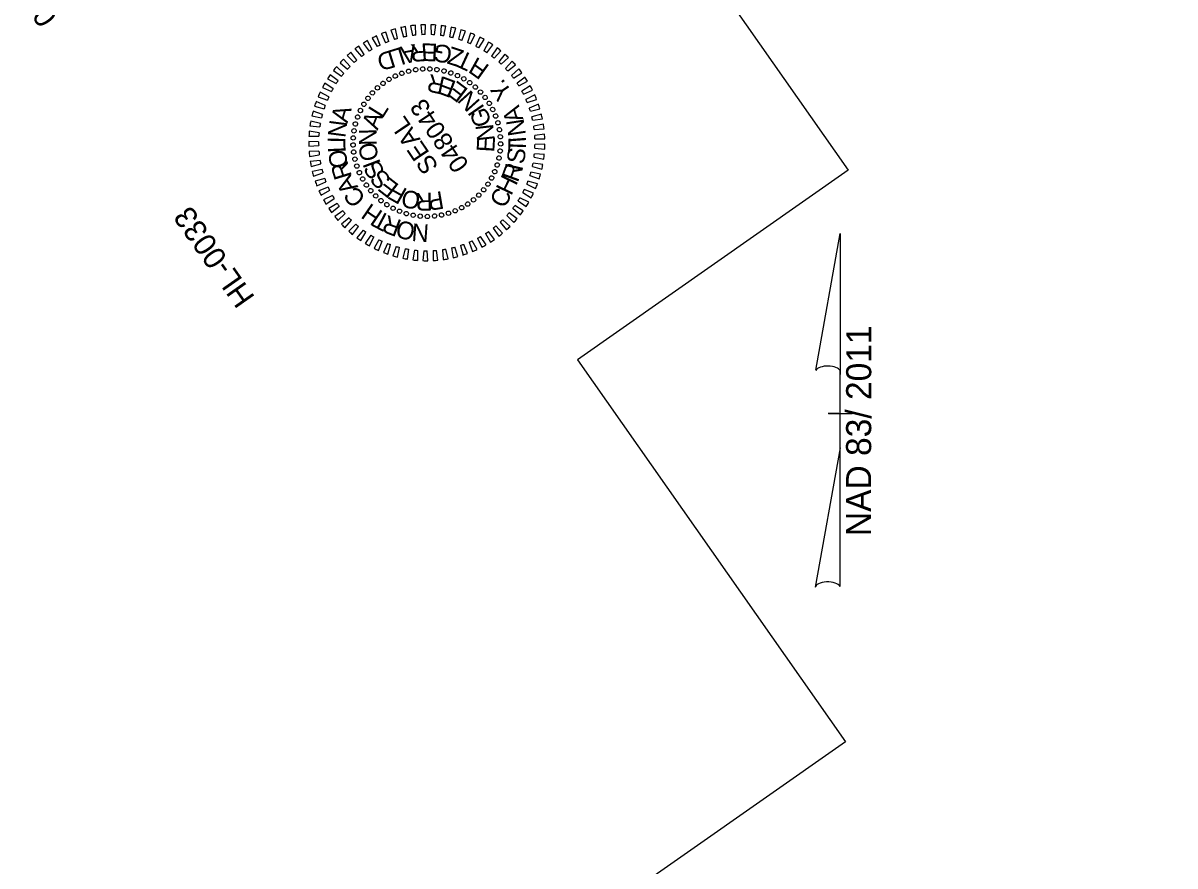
# Model space of a CAD drawing. Extents: x 2046262 to 2047823, y 758628 to 760417.
# Drawn here: x 2046261.8 to 2046652, y 759522.5 to 759808.2 of the extents above; entities that cross this region are included whole.
import ezdxf

# ---------------------------------------------------------------- set-up
doc = ezdxf.new("R2010")
doc.units = 0
for name, color, linetype in [('Prop North Arrow NAD83 for Plan Sheets CELL', 7, 'Continuous'), ('Sheet Clip Boundary CELL', 7, 'Continuous'), ('Sheet Data Field CELL', 7, 'Continuous'), ('Sheet PE Seal Cell', 7, 'Continuous')]:
    doc.layers.add(name, color=color, linetype=linetype)

msp = doc.modelspace()

# ---------------------------------------------------------------- linework, layer by layer
at = {"layer": 'Prop North Arrow NAD83 for Plan Sheets CELL'}
for p, q in [((2046530.36, 759690.47), (2046538.6, 759736.81)), ((2046538.65, 759736.81), (2046538.6, 759736.81)), ((2046538.65, 759736.81), (2046538.6, 759736.81)), ((2046538.65, 759736.81), (2046538.6, 759689.01)), ((2046538.58, 759664.21), (2046538.61, 759690.41)), ((2046538.6, 759689.01), (2046538.61, 759690.36)), ((2046534.59, 759675.81), (2046534.54, 759675.81)), ((2046538.14, 759675.81), (2046534.59, 759675.81)), ((2046534.64, 759675.81), (2046542.64, 759675.8)), ((2046538.58, 759664.21), (2046530.18, 759616.97)), ((2046538.58, 759617.16), (2046538.58, 759664.21))]:
    msp.add_line(p, q, dxfattribs=at)
for centre, start_param, end_param in [((2046534.49, 759689.97), 0.216388, 2.908219), ((2046534.41, 759616.8), 0.201328, 3.141593)]:
    msp.add_ellipse(centre, major_axis=(4.23, -0.03), ratio=0.461098, start_param=start_param, end_param=end_param, dxfattribs=at)
at = {"layer": 'Sheet Clip Boundary CELL'}
msp.add_lwpolyline([(2046953.28, 758800.94), (2047822.73, 759389.82), (2047107.57, 760411.26), (2046421.17, 759929.65), (2046541.36, 759758.35), (2046449.64, 759693.99), (2046540.41, 759564.59), (2046459.01, 759507.49)], close=True, dxfattribs=at)
at = {"layer": 'Sheet PE Seal Cell'}
for p, q in [((2046383.16, 759804.53), (2046384.61, 759801.51)), ((2046385.69, 759801.93), (2046384.69, 759805.13)), ((2046386.39, 759805.72), (2046387.58, 759802.58)), ((2046388.68, 759802.91), (2046387.97, 759806.19)), ((2046389.71, 759806.63), (2046390.63, 759803.4)), ((2046391.75, 759803.63), (2046391.32, 759806.96)), ((2046393.09, 759807.24), (2046393.73, 759803.95)), ((2046394.87, 759804.08), (2046394.73, 759807.44)), ((2046396.52, 759807.57), (2046396.87, 759804.23)), ((2046398.02, 759804.27), (2046398.17, 759807.62)), ((2046399.96, 759807.6), (2046400.03, 759804.24)), ((2046401.17, 759804.18), (2046401.61, 759807.51)), ((2046403.39, 759807.33), (2046403.17, 759803.98)), ((2046404.31, 759803.82), (2046405.03, 759807.1)), ((2046406.79, 759806.77), (2046406.28, 759803.45)), ((2046407.4, 759803.19), (2046408.4, 759806.4)), ((2046410.12, 759805.92), (2046409.33, 759802.66)), ((2046410.42, 759802.3), (2046411.69, 759805.41)), ((2046413.37, 759804.78), (2046412.3, 759801.6)), ((2046413.36, 759801.16), (2046414.89, 759804.14)), ((2046377.35, 759797.5), (2046375.57, 759800.35)), ((2046377.06, 759801.34), (2046379.02, 759798.62)), ((2046380, 759799.21), (2046378.47, 759802.2)), ((2046380.04, 759803.07), (2046381.75, 759800.18)), ((2046382.78, 759800.69), (2046381.52, 759803.8)), ((2046416.51, 759803.37), (2046415.17, 759800.3)), ((2046416.19, 759799.76), (2046417.97, 759802.6)), ((2046419.52, 759801.7), (2046417.92, 759798.75)), ((2046418.89, 759798.13), (2046420.91, 759800.81)), ((2046371.6, 759797.16), (2046374, 759794.81)), ((2046374.86, 759795.57), (2046372.84, 759798.25)), ((2046374.24, 759799.37), (2046376.42, 759796.82)), ((2046422.37, 759799.77), (2046420.52, 759796.97)), ((2046421.43, 759796.27), (2046423.68, 759798.76)), ((2046425.05, 759797.61), (2046422.97, 759794.98)), ((2046423.81, 759794.2), (2046426.26, 759796.49)), ((2046370.43, 759791.09), (2046367.98, 759793.39)), ((2046369.16, 759794.73), (2046371.75, 759792.59)), ((2046372.55, 759793.42), (2046370.31, 759795.92)), ((2046427.53, 759795.22), (2046425.23, 759792.78)), ((2046426, 759791.93), (2046428.64, 759794)), ((2046429.79, 759792.63), (2046427.29, 759790.39)), ((2046364.95, 759789.29), (2046367.87, 759787.63)), ((2046368.51, 759788.58), (2046365.88, 759790.66)), ((2046366.94, 759792.1), (2046369.7, 759790.2)), ((2046427.99, 759789.48), (2046430.8, 759791.32)), ((2046431.83, 759789.85), (2046429.14, 759787.84)), ((2046429.76, 759786.87), (2046432.72, 759788.46)), ((2046365.37, 759783.12), (2046362.41, 759784.72)), ((2046363.22, 759786.32), (2046366.26, 759784.92)), ((2046366.82, 759785.92), (2046364.02, 759787.77)), ((2046433.61, 759786.91), (2046430.77, 759785.14)), ((2046431.3, 759784.12), (2046434.38, 759785.45)), ((2046364.16, 759780.21), (2046361.08, 759781.55)), ((2046361.74, 759783.21), (2046364.9, 759782.07)), ((2046435.14, 759783.83), (2046432.15, 759782.31)), ((2046432.6, 759781.25), (2046435.78, 759782.31)), ((2046436.4, 759780.63), (2046433.29, 759779.36)), ((2046359.61, 759776.67), (2046362.92, 759776.09)), ((2046363.2, 759777.21), (2046360.02, 759778.27)), ((2046360.54, 759779.99), (2046363.78, 759779.13)), ((2046433.64, 759778.27), (2046436.91, 759779.05)), ((2046437.38, 759777.33), (2046434.17, 759776.34)), ((2046358.98, 759773.29), (2046362.32, 759773)), ((2046362.51, 759774.13), (2046359.25, 759774.92)), ((2046434.43, 759775.22), (2046437.75, 759775.72)), ((2046438.07, 759773.95), (2046434.79, 759773.24)), ((2046358.64, 759769.87), (2046361.99, 759769.86)), ((2046362.08, 759771.01), (2046358.76, 759771.51)), ((2046434.95, 759772.11), (2046438.3, 759772.32)), ((2046438.47, 759770.53), (2046435.14, 759770.11)), ((2046435.2, 759768.96), (2046438.55, 759768.89)), ((2046361.93, 759767.86), (2046358.58, 759768.07)), ((2046358.59, 759766.42), (2046361.94, 759766.71)), ((2046398.57, 759767.62), (2046398.57, 759767.62)), ((2046435.18, 759765.81), (2046438.52, 759765.45)), ((2046438.57, 759767.09), (2046435.22, 759766.96)), ((2046362.04, 759764.7), (2046358.69, 759764.63)), ((2046358.84, 759762.99), (2046362.15, 759763.56)), ((2046362.43, 759761.57), (2046359.09, 759761.22)), ((2046434.89, 759762.67), (2046438.18, 759762.02)), ((2046438.38, 759763.66), (2046435.03, 759763.81)), ((2046359.39, 759759.59), (2046362.63, 759760.44)), ((2046363.08, 759758.49), (2046359.79, 759757.85)), ((2046360.22, 759756.25), (2046363.38, 759757.38)), ((2046437.11, 759756.9), (2046433.83, 759757.62)), ((2046434.33, 759759.56), (2046437.55, 759758.64)), ((2046437.89, 759760.25), (2046434.56, 759760.69)), ((2046364, 759755.47), (2046360.77, 759754.55)), ((2046361.34, 759753), (2046364.39, 759754.39)), ((2046432.42, 759753.56), (2046435.44, 759752.09)), ((2046436.05, 759753.63), (2046432.84, 759754.63)), ((2046433.5, 759756.52), (2046436.64, 759755.32)), ((2046365.17, 759752.54), (2046362.03, 759751.35)), ((2046362.74, 759749.85), (2046365.66, 759751.5)), ((2046366.59, 759749.73), (2046363.57, 759748.27)), ((2046431.09, 759750.7), (2046433.97, 759748.98)), ((2046434.7, 759750.46), (2046431.6, 759751.73)), ((2046364.4, 759746.84), (2046367.17, 759748.73)), ((2046368.24, 759747.05), (2046365.36, 759745.33)), ((2046366.31, 759743.98), (2046368.91, 759746.1)), ((2046427.71, 759745.38), (2046430.25, 759743.19)), ((2046431.23, 759744.52), (2046428.39, 759746.31)), ((2046429.51, 759747.97), (2046432.23, 759746.01)), ((2046433.1, 759747.41), (2046430.11, 759748.95)), ((2046370.13, 759744.51), (2046367.4, 759742.56)), ((2046368.46, 759741.29), (2046370.86, 759743.63)), ((2046372.22, 759742.15), (2046369.67, 759739.97)), ((2046426.79, 759739.27), (2046424.3, 759741.52)), ((2046425.69, 759742.96), (2046428.03, 759740.56)), ((2046429.12, 759741.8), (2046426.45, 759743.82)), ((2046370.84, 759738.8), (2046373.03, 759741.34)), ((2046374.5, 759739.98), (2046372.16, 759737.59)), ((2046373.42, 759736.52), (2046375.38, 759739.24)), ((2046376.97, 759738.02), (2046374.84, 759735.43)), ((2046421.52, 759734.85), (2046419.45, 759737.5)), ((2046421.06, 759738.68), (2046422.96, 759735.92)), ((2046424.25, 759736.95), (2046421.96, 759739.4)), ((2046423.47, 759740.72), (2046425.6, 759738.13)), ((2046376.18, 759734.47), (2046377.91, 759737.35)), ((2046379.59, 759736.27), (2046377.69, 759733.5)), ((2046379.12, 759732.67), (2046380.59, 759735.69)), ((2046382.36, 759734.75), (2046380.7, 759731.84)), ((2046382.19, 759731.13), (2046383.4, 759734.26)), ((2046412.93, 759733.9), (2046414.06, 759730.74)), ((2046415.57, 759731.41), (2046413.98, 759734.36)), ((2046415.77, 759735.26), (2046417.17, 759732.21)), ((2046418.62, 759733), (2046416.78, 759735.81)), ((2046418.49, 759736.86), (2046420.15, 759733.94)), ((2046385.25, 759733.48), (2046383.84, 759730.43)), ((2046385.39, 759729.86), (2046386.32, 759733.08)), ((2046388.23, 759732.46), (2046387.09, 759729.3)), ((2046388.68, 759728.86), (2046389.34, 759732.15)), ((2046391.29, 759731.7), (2046390.43, 759728.46)), ((2046392.05, 759728.16), (2046392.42, 759731.49)), ((2046394.41, 759731.21), (2046393.83, 759727.9)), ((2046395.47, 759727.74), (2046395.55, 759731.1)), ((2046397.55, 759730.98), (2046397.26, 759727.64)), ((2046398.91, 759727.62), (2046398.7, 759730.97)), ((2046400.7, 759731.03), (2046400.7, 759727.68)), ((2046402.35, 759727.8), (2046401.85, 759731.12)), ((2046403.84, 759731.35), (2046404.13, 759728.01)), ((2046405.76, 759728.27), (2046404.98, 759731.53)), ((2046406.94, 759731.94), (2046407.51, 759728.63)), ((2046409.11, 759729.03), (2046408.05, 759732.22)), ((2046409.98, 759732.79), (2046410.83, 759729.54)), ((2046412.39, 759730.08), (2046411.06, 759733.16))]:
    msp.add_line(p, q, dxfattribs=at)
for radius, start, end in [(40, 110.308, 112.6716), (40, 105.3765, 107.7401), (40, 100.445, 102.8086), (40, 95.5135, 97.8771), (36.65, 95.7963, 97.5942), (40, 90.5819, 92.9456), (36.65, 90.8648, 92.6627), (40, 85.6504, 88.0141), (36.65, 85.9333, 87.7312), (36.65, 81.0018, 82.7997), (40, 80.7189, 83.0825), (40, 75.7874, 78.151), (40, 70.8559, 73.2195), (40, 65.9244, 68.288), (40, 125.1025, 127.4661), (40, 120.171, 122.5346), (40, 115.2395, 117.6031), (36.65, 115.5223, 117.3202), (36.65, 110.5908, 112.3887), (36.65, 105.6593, 107.4572), (36.65, 100.7278, 102.5257), (36.65, 76.0703, 77.8682), (36.65, 71.1388, 72.9367), (36.65, 66.2073, 68.0052), (36.65, 61.2758, 63.0737), (40, 60.9929, 63.3565), (40, 56.0614, 58.425), (40, 130.034, 132.3976), (36.65, 125.3854, 127.1832), (36.65, 120.4538, 122.2517), (36.65, 56.3443, 58.1422), (36.65, 51.4128, 53.2106), (40, 51.1299, 53.4935), (40, 46.1984, 48.562), (40, 139.897, 142.2606), (40, 134.9655, 137.3291), (36.65, 135.2484, 137.0463), (36.65, 130.3169, 132.1148), (36.65, 46.4812, 48.2791), (36.65, 41.5497, 43.3476), (40, 41.2669, 43.6305), (40, 36.3354, 38.699), (40, 144.8285, 147.1921), (36.65, 145.1114, 146.9093), (36.65, 140.1799, 141.9778), (36.65, 36.6182, 38.4161), (40, 31.4039, 33.7675), (40, 154.6915, 157.0552), (40, 149.76, 152.1236), (36.65, 150.0429, 151.8408), (36.65, 31.6867, 33.4846), (36.65, 26.7552, 28.5531), (40, 26.4724, 28.836), (40, 159.623, 161.9867), (36.65, 154.9744, 156.7723), (36.65, 21.8237, 23.6216), (40, 21.5408, 23.9045), (40, 16.6093, 18.973), (40, 164.5545, 166.9182), (36.65, 164.8374, 166.6353), (36.65, 159.9059, 161.7038), (36.65, 16.8922, 18.6901), (40, 11.6778, 14.0415), (40, 169.4861, 171.8497), (36.65, 169.7689, 171.5668), (36.65, 11.9607, 13.7586), (36.65, 7.0292, 8.8271), (40, 6.7463, 9.1099), (40, 174.4176, 176.7812), (36.65, 174.7004, 176.4983), (36.65, 2.0977, 3.8956), (40, 1.8148, 4.1784), (40, 179.3491, 181.7127), (36.65, 179.6319, 181.4298), (36.65, 357.1662, 358.9641), (40, 356.8833, 359.2469), (40, 184.2806, 186.6442), (40, 189.2121, 191.5757), (36.65, 184.5634, 186.3613), (36.65, 189.4949, 191.2928), (36.65, 352.2347, 354.0326), (40, 351.9518, 354.3154), (40, 194.1436, 196.5072), (36.65, 194.4264, 196.2243), (36.65, 342.3717, 344.1695), (36.65, 347.3032, 349.1011), (40, 347.0203, 349.3839), (40, 199.0751, 201.4387), (36.65, 199.358, 201.1559), (36.65, 337.4401, 339.238), (40, 337.1573, 339.5209), (40, 342.0888, 344.4524), (40, 204.0066, 206.3702), (36.65, 204.2895, 206.0874), (36.65, 209.221, 211.0189), (36.65, 332.5086, 334.3065), (40, 332.2258, 334.5894), (40, 208.9381, 211.3017), (40, 213.8696, 216.2332), (36.65, 214.1525, 215.9504), (36.65, 322.6456, 324.4435), (36.65, 327.5771, 329.375), (40, 327.2943, 329.6579), (40, 218.8011, 221.1647), (36.65, 219.084, 220.8819), (36.65, 224.0155, 225.8134), (36.65, 312.7826, 314.5805), (36.65, 317.7141, 319.512), (40, 317.4313, 319.7949), (40, 322.3628, 324.7264), (40, 223.7326, 226.0962), (40, 228.6641, 231.0278), (36.65, 228.947, 230.7449), (36.65, 233.8785, 235.6764), (36.65, 302.9196, 304.7175), (36.65, 307.8511, 309.649), (40, 312.4998, 314.8634), (40, 233.5956, 235.9593), (36.65, 238.81, 240.6079), (36.65, 243.7415, 245.5394), (36.65, 293.0566, 294.8545), (36.65, 297.9881, 299.786), (40, 302.6367, 305.0004), (40, 307.5682, 309.9319), (40, 238.5271, 240.8908), (40, 243.4587, 245.8223), (40, 248.3902, 250.7538), (36.65, 248.673, 250.4709), (36.65, 253.6045, 255.4024), (36.65, 258.536, 260.3339), (36.65, 263.4675, 265.2654), (36.65, 268.3991, 270.1969), (36.65, 273.3306, 275.1285), (36.65, 278.2621, 280.06), (36.65, 283.1936, 284.9915), (36.65, 288.1251, 289.923), (40, 287.8422, 290.2058), (40, 292.7737, 295.1373), (40, 297.7052, 300.0688), (40, 253.3217, 255.6853), (40, 258.2532, 260.6168), (40, 263.1847, 265.5483), (40, 268.1162, 270.4798), (40, 273.0477, 275.4113), (40, 277.9792, 280.3428), (40, 282.9107, 285.2743)]:
    msp.add_arc((2046398.57, 759767.62), radius, start, end, dxfattribs=at)
for centre, major_axis in [((2046392.41, 759791.85), (-0.233, 0.705)), ((2046394.77, 759792.33), (-0.164, 0.724)), ((2046397.18, 759792.58), (-0.093, 0.736)), ((2046399.59, 759792.6), (-0.022, 0.742)), ((2046402, 759792.38), (0.05, 0.741)), ((2046404.37, 759791.94), (0.121, 0.732)), ((2046383.73, 759787.73), (-0.481, 0.565)), ((2046385.74, 759789.07), (-0.425, 0.609)), ((2046387.87, 759790.21), (-0.364, 0.647)), ((2046390.1, 759791.14), (-0.3, 0.679)), ((2046406.69, 759791.27), (0.191, 0.717)), ((2046408.94, 759790.37), (0.26, 0.695)), ((2046411.08, 759789.27), (0.326, 0.667)), ((2046413.11, 759787.96), (0.389, 0.633)), ((2046380.14, 759784.51), (-0.581, 0.462)), ((2046381.85, 759786.21), (-0.534, 0.516)), ((2046415.01, 759786.46), (0.448, 0.592)), ((2046416.75, 759784.78), (0.503, 0.546)), ((2046377.24, 759780.65), (-0.659, 0.342)), ((2046378.6, 759782.65), (-0.623, 0.404)), ((2046418.32, 759782.95), (0.553, 0.495)), ((2046419.71, 759780.97), (0.598, 0.439)), ((2046375.13, 759776.31), (-0.712, 0.209)), ((2046376.08, 759778.53), (-0.689, 0.277)), ((2046420.9, 759778.87), (0.638, 0.379)), ((2046421.88, 759776.66), (0.672, 0.316)), ((2046374.4, 759774), (-0.729, 0.139)), ((2046422.65, 759774.37), (0.699, 0.25)), ((2046423.18, 759772.02), (0.72, 0.181)), ((2046373.63, 759769.24), (-0.742, -0.004)), ((2046373.9, 759771.64), (-0.739, 0.068)), ((2046423.49, 759769.62), (0.734, 0.111)), ((2046373.59, 759766.83), (-0.739, -0.075)), ((2046373.78, 759764.42), (-0.728, -0.146)), ((2046423.41, 759764.8), (0.742, -0.032)), ((2046423.57, 759767.21), (0.741, 0.04)), ((2046374.21, 759762.04), (-0.71, -0.216)), ((2046423.03, 759762.41), (0.735, -0.104)), ((2046374.86, 759759.71), (-0.686, -0.283)), ((2046375.73, 759757.46), (-0.656, -0.348)), ((2046421.57, 759757.81), (0.701, -0.243)), ((2046422.41, 759760.08), (0.722, -0.174)), ((2046376.82, 759755.3), (-0.619, -0.41)), ((2046378.11, 759753.26), (-0.576, -0.468)), ((2046419.26, 759753.58), (0.642, -0.373)), ((2046420.52, 759755.64), (0.675, -0.31)), ((2046379.59, 759751.35), (-0.529, -0.521)), ((2046381.25, 759749.6), (-0.476, -0.57)), ((2046416.17, 759749.86), (0.558, -0.49)), ((2046417.8, 759751.65), (0.603, -0.433)), ((2046383.07, 759748.01), (-0.419, -0.613)), ((2046385.03, 759746.6), (-0.358, -0.651)), ((2046387.13, 759745.4), (-0.293, -0.682)), ((2046408.18, 759744.54), (0.332, -0.664)), ((2046410.36, 759745.57), (0.395, -0.629)), ((2046412.43, 759746.81), (0.454, -0.588)), ((2046414.38, 759748.25), (0.508, -0.541)), ((2046389.32, 759744.39), (-0.226, -0.707)), ((2046391.61, 759743.61), (-0.157, -0.726)), ((2046393.96, 759743.05), (-0.086, -0.737)), ((2046396.35, 759742.72), (-0.014, -0.742)), ((2046398.76, 759742.62), (0.057, -0.74)), ((2046401.18, 759742.76), (0.129, -0.731)), ((2046403.56, 759743.12), (0.199, -0.715)), ((2046405.91, 759743.72), (0.267, -0.693))]:
    msp.add_ellipse(centre, major_axis=major_axis, ratio=0.999708, dxfattribs=at)

# ---------------------------------------------------------------- texts
at = {"layer": 'Prop North Arrow NAD83 for Plan Sheets CELL'}
msp.add_text('NAD 83/ 2011', height=8.5, rotation=89.9391, dxfattribs=at).set_placement((2046549.07, 759634.28))
at = {"layer": 'Sheet Data Field CELL'}
for s, p in [('06', (2046273.82, 759810.32)), ('HL-0033', (2046340.55, 759715.19))]:
    msp.add_text(s, height=7.5, rotation=125.0179, dxfattribs=at).set_placement(p)
at = {"layer": 'Sheet PE Seal Cell'}
for s, height, rotation, p in [('L', 6, 197.1035, (2046390.08, 759800.19)), ('A', 6, 190.9873, (2046394.53, 759801.09)), ('R', 6, 184.165, (2046398.53, 759801.33)), ('E', 6, 177.5904, (2046402.39, 759801.12)), ('G', 6, 168.5998, (2046407.58, 759800.11)), ('Z', 6, 161.6329, (2046411.45, 759798.77)), ('D', 6, 197.1035, (2046386.7, 759799.15)), ('T', 6, 155.2648, (2046414.83, 759797.15)), ('I', 6, 150.8997, (2046417.03, 759795.83)), ('F', 6, 144.3871, (2046420.11, 759793.55)), ('R', 6, 168.0491, (2046405.05, 759789.76)), ('E', 6, 159.2961, (2046408.88, 759788.28)), ('E', 6, 142.8924, (2046412.92, 759785.6)), ('.', 6, 131.2276, (2046425.45, 759787.97)), ('N', 6, 132.0432, (2046416.96, 759781.57)), ('Y', 6, 124.1161, (2046427.76, 759784.48)), ('048043', 6.185, 124.0514, (2046413.08, 759760.24)), ('I', 6, 124.5937, (2046418.33, 759779.45)), ('A', 6, 107.7457, (2046431.33, 759775.57)), ('A', 6, 73.7281, (2046371.67, 759774.03)), ('A', 6, 68.2732, (2046381.89, 759771.64)), ('L', 6, 58.1401, (2046383.5, 759775.56)), ('SEAL', 6.184, 124.0514, (2046402.75, 759759.6)), ('G', 6, 109.009, (2046420.62, 759774.16)), ('N', 6, 82.6584, (2046370.92, 759769.11)), ('N', 6, 96.4793, (2046421.62, 759768.49)), ('N', 6, 98.7551, (2046432.17, 759770.35)), ('I', 6, 88.4949, (2046370.94, 759767.38)), ('N', 6, 90.7935, (2046381.62, 759766.65)), ('E', 6, 86.6258, (2046421.4, 759764.26)), ('T', 6, 88.0219, (2046432.09, 759764.04)), ('I', 6, 94.39, (2046432.28, 759767.78)), ('L', 6, 92.4825, (2046371.09, 759764.31)), ('O', 6, 99.6828, (2046371.96, 759759.54)), ('O', 6, 102.507, (2046382.39, 759762.11)), ('S', 6, 81.3028, (2046431.45, 759760.14)), ('R', 6, 106.9721, (2046373.25, 759756.22)), ('I', 6, 110.8969, (2046383.08, 759760.57)), ('S', 6, 125.0568, (2046384.67, 759757.92)), ('A', 6, 122.4593, (2046375.44, 759752.6)), ('S', 6, 133.437, (2046386.84, 759755.29)), ('R', 6, 70.1153, (2046429.37, 759753.91)), ('I', 6, 76.9377, (2046430.78, 759757.66)), ('E', 6, 142.2361, (2046389.48, 759753.17)), ('H', 6, 64.2875, (2046427.14, 759749.44)), ('C', 6, 131.3437, (2046378.22, 759748.98)), ('F', 6, 150.4633, (2046392.32, 759751.66)), ('O', 6, 169.411, (2046396.77, 759750.68)), ('R', 6, 181.3373, (2046400.48, 759750.66)), ('P', 6, 189.8445, (2046403.71, 759751.28)), ('C', 6, 64.2875, (2046425.05, 759745.09)), ('H', 6, 145.7126, (2046384.05, 759744.1)), ('T', 6, 152.1057, (2046386.78, 759742.61)), ('R', 6, 159.2027, (2046390.4, 759741.18)), ('O', 6, 166.8653, (2046395.09, 759740.08)), ('N', 6, 175.885, (2046399.48, 759739.88))]:
    msp.add_text(s, height=height, rotation=rotation, dxfattribs=at).set_placement(p)

doc.saveas('drawing.dxf')
